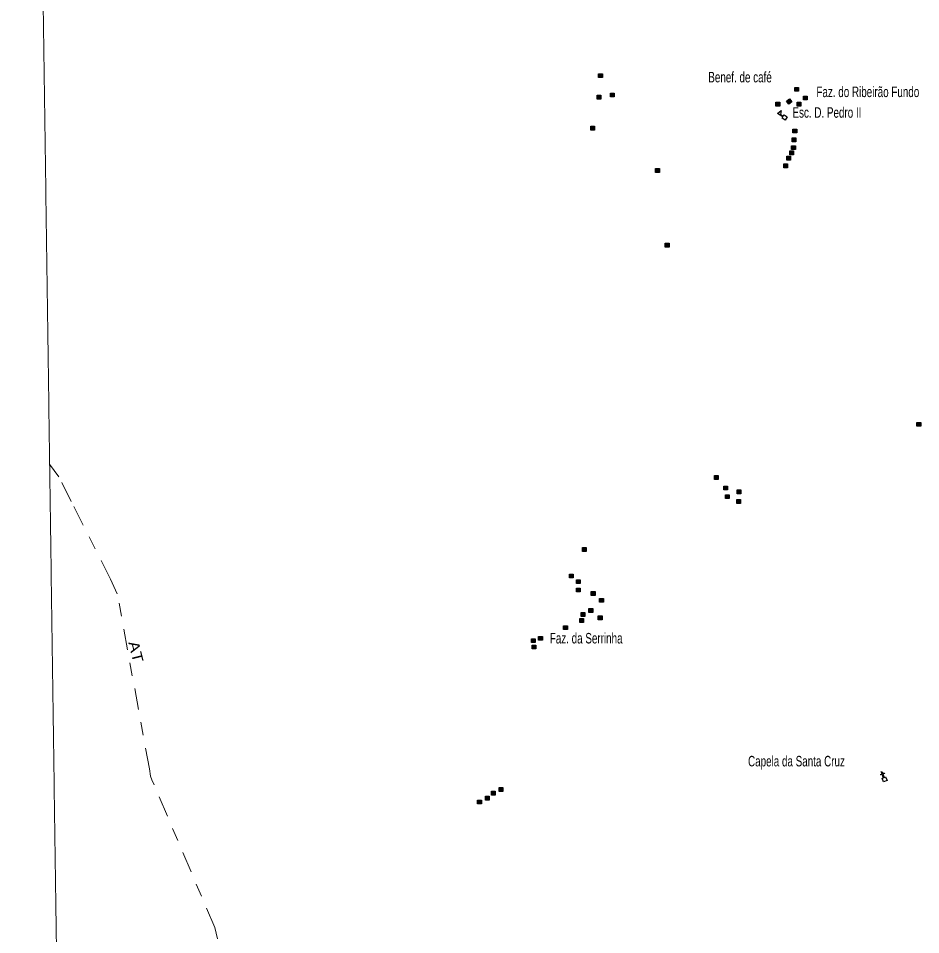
# Model space of a CAD drawing. Extents: x 265.7 to 292.1, y 7676.2 to 7704.2.
# Drawn here: x 265.72 to 272.58, y 7683.22 to 7690.19 of the extents above; entities that cross this region are included whole.
import ezdxf
from ezdxf.enums import TextEntityAlignment as Align

# ---------------------------------------------------------------- set-up
doc = ezdxf.new("R2010")
doc.units = 0
doc.header["$LTSCALE"] = 0.032
doc.linetypes.add('DOT_DASHED', pattern=[7.7, 5, -1.2, 0.3, -1.2])
for name, color, linetype, lineweight in [('2', 7, 'Continuous', 25), ('4', 7, 'Continuous', 25), ('56', 7, 'DOT_DASHED', 13), ('6', 7, 'Continuous', 25), ('63', 7, 'Continuous', 13)]:
    doc.layers.add(name, color=color, linetype=linetype, lineweight=lineweight)
doc.layers.add('61', color=7, linetype='Continuous')

msp = doc.modelspace()

# ---------------------------------------------------------------- hatches: boundary and pattern name
at = {"layer": '2'}
for points in [[(270.1334, 7689.7687), (270.1624, 7689.7687), (270.1624, 7689.7397), (270.1334, 7689.7397)], [(271.6248, 7689.6646), (271.6538, 7689.6646), (271.6538, 7689.6356), (271.6248, 7689.6356)], [(270.1213, 7689.6056), (270.1503, 7689.6056), (270.1503, 7689.5766), (270.1213, 7689.5766)], [(270.2228, 7689.6219), (270.2518, 7689.6219), (270.2518, 7689.5929), (270.2228, 7689.5929)], [(271.5633, 7689.5606), (271.5863, 7689.5783), (271.6039, 7689.5552), (271.5809, 7689.5376)], [(271.6917, 7689.5993), (271.7207, 7689.5993), (271.7207, 7689.5703), (271.6917, 7689.5703)], [(271.4819, 7689.5525), (271.5109, 7689.5525), (271.5109, 7689.5235), (271.4819, 7689.5235)], [(271.6425, 7689.5523), (271.6715, 7689.5523), (271.6715, 7689.5233), (271.6425, 7689.5233)], [(270.0728, 7689.37), (270.1018, 7689.37), (270.1018, 7689.341), (270.0728, 7689.341)], [(271.6118, 7689.3482), (271.6408, 7689.3482), (271.6408, 7689.3192), (271.6118, 7689.3192)], [(271.6013, 7689.2216), (271.6303, 7689.2216), (271.6303, 7689.1926), (271.6013, 7689.1926)], [(271.6046, 7689.2804), (271.6336, 7689.2804), (271.6336, 7689.2514), (271.6046, 7689.2514)], [(271.5876, 7689.1819), (271.6166, 7689.1819), (271.6166, 7689.1529), (271.5876, 7689.1529)], [(271.5416, 7689.0828), (271.5706, 7689.0828), (271.5706, 7689.0538), (271.5416, 7689.0538)], [(271.565, 7689.1409), (271.594, 7689.1409), (271.594, 7689.1119), (271.565, 7689.1119)], [(270.5666, 7689.0472), (270.5956, 7689.0472), (270.5956, 7689.0182), (270.5666, 7689.0182)], [(270.6402, 7688.4798), (270.6692, 7688.4798), (270.6692, 7688.4508), (270.6402, 7688.4508)], [(272.5544, 7687.1167), (272.5834, 7687.1167), (272.5834, 7687.0877), (272.5544, 7687.0877)], [(271.0146, 7686.7124), (271.0436, 7686.7124), (271.0436, 7686.6834), (271.0146, 7686.6834)], [(271.0856, 7686.6326), (271.1146, 7686.6326), (271.1146, 7686.6036), (271.0856, 7686.6036)], [(271.1868, 7686.6028), (271.2158, 7686.6028), (271.2158, 7686.5738), (271.1868, 7686.5738)], [(271.0984, 7686.567), (271.1274, 7686.567), (271.1274, 7686.538), (271.0984, 7686.538)], [(271.1842, 7686.5301), (271.2132, 7686.5301), (271.2132, 7686.5011), (271.1842, 7686.5011)], [(270.0099, 7686.1652), (270.0389, 7686.1652), (270.0389, 7686.1362), (270.0099, 7686.1362)], [(269.9106, 7685.9628), (269.9396, 7685.9628), (269.9396, 7685.9338), (269.9106, 7685.9338)], [(269.9638, 7685.9199), (269.9928, 7685.9199), (269.9928, 7685.8909), (269.9638, 7685.8909)], [(269.9638, 7685.857), (269.9928, 7685.857), (269.9928, 7685.828), (269.9638, 7685.828)], [(270.0776, 7685.8296), (270.1066, 7685.8296), (270.1066, 7685.8006), (270.0776, 7685.8006)], [(270.1406, 7685.7778), (270.1696, 7685.7778), (270.1696, 7685.7488), (270.1406, 7685.7488)], [(269.9994, 7685.6705), (270.0284, 7685.6705), (270.0284, 7685.6415), (269.9994, 7685.6415)], [(270.0592, 7685.7004), (270.0882, 7685.7004), (270.0882, 7685.6714), (270.0592, 7685.6714)], [(269.9896, 7685.6251), (270.0186, 7685.6251), (270.0186, 7685.5961), (269.9896, 7685.5961)], [(270.1308, 7685.645), (270.1598, 7685.645), (270.1598, 7685.616), (270.1308, 7685.616)], [(269.8662, 7685.5697), (269.8952, 7685.5697), (269.8952, 7685.5407), (269.8662, 7685.5407)], [(269.6217, 7685.4712), (269.6507, 7685.4712), (269.6507, 7685.4422), (269.6217, 7685.4422)], [(269.6762, 7685.4885), (269.7052, 7685.4885), (269.7052, 7685.4595), (269.6762, 7685.4595)], [(269.6266, 7685.4235), (269.6556, 7685.4235), (269.6556, 7685.3945), (269.6266, 7685.3945)], [(269.2722, 7684.2735), (269.3012, 7684.2735), (269.3012, 7684.2445), (269.2722, 7684.2445)], [(269.3174, 7684.3107), (269.3464, 7684.3107), (269.3464, 7684.2817), (269.3174, 7684.2817)], [(269.3754, 7684.3396), (269.4044, 7684.3396), (269.4044, 7684.3106), (269.3754, 7684.3106)], [(269.2125, 7684.2445), (269.2415, 7684.2445), (269.2415, 7684.2155), (269.2125, 7684.2155)]]:
    msp.add_hatch(color=256, dxfattribs=at).paths.add_polyline_path(points)

# ---------------------------------------------------------------- linework, layer by layer
for points in [[(270.1334, 7689.7687), (270.1624, 7689.7687), (270.1624, 7689.7397), (270.1334, 7689.7397)], [(271.6248, 7689.6646), (271.6538, 7689.6646), (271.6538, 7689.6356), (271.6248, 7689.6356)], [(270.1213, 7689.6056), (270.1503, 7689.6056), (270.1503, 7689.5766), (270.1213, 7689.5766)], [(270.2228, 7689.6219), (270.2518, 7689.6219), (270.2518, 7689.5929), (270.2228, 7689.5929)], [(271.5633, 7689.5606), (271.5863, 7689.5783), (271.6039, 7689.5552), (271.5809, 7689.5376)], [(271.6917, 7689.5993), (271.7207, 7689.5993), (271.7207, 7689.5703), (271.6917, 7689.5703)], [(271.4819, 7689.5525), (271.5109, 7689.5525), (271.5109, 7689.5235), (271.4819, 7689.5235)], [(271.6425, 7689.5523), (271.6715, 7689.5523), (271.6715, 7689.5233), (271.6425, 7689.5233)], [(270.0728, 7689.37), (270.1018, 7689.37), (270.1018, 7689.341), (270.0728, 7689.341)], [(271.6118, 7689.3482), (271.6408, 7689.3482), (271.6408, 7689.3192), (271.6118, 7689.3192)], [(271.6013, 7689.2216), (271.6303, 7689.2216), (271.6303, 7689.1926), (271.6013, 7689.1926)], [(271.6046, 7689.2804), (271.6336, 7689.2804), (271.6336, 7689.2514), (271.6046, 7689.2514)], [(271.5876, 7689.1819), (271.6166, 7689.1819), (271.6166, 7689.1529), (271.5876, 7689.1529)], [(271.5416, 7689.0828), (271.5706, 7689.0828), (271.5706, 7689.0538), (271.5416, 7689.0538)], [(271.565, 7689.1409), (271.594, 7689.1409), (271.594, 7689.1119), (271.565, 7689.1119)], [(270.5666, 7689.0472), (270.5956, 7689.0472), (270.5956, 7689.0182), (270.5666, 7689.0182)], [(270.6402, 7688.4798), (270.6692, 7688.4798), (270.6692, 7688.4508), (270.6402, 7688.4508)], [(272.5544, 7687.1167), (272.5834, 7687.1167), (272.5834, 7687.0877), (272.5544, 7687.0877)], [(271.0146, 7686.7124), (271.0436, 7686.7124), (271.0436, 7686.6834), (271.0146, 7686.6834)], [(271.0856, 7686.6326), (271.1146, 7686.6326), (271.1146, 7686.6036), (271.0856, 7686.6036)], [(271.1868, 7686.6028), (271.2158, 7686.6028), (271.2158, 7686.5738), (271.1868, 7686.5738)], [(271.0984, 7686.567), (271.1274, 7686.567), (271.1274, 7686.538), (271.0984, 7686.538)], [(271.1842, 7686.5301), (271.2132, 7686.5301), (271.2132, 7686.5011), (271.1842, 7686.5011)], [(270.0099, 7686.1652), (270.0389, 7686.1652), (270.0389, 7686.1362), (270.0099, 7686.1362)], [(269.9106, 7685.9628), (269.9396, 7685.9628), (269.9396, 7685.9338), (269.9106, 7685.9338)], [(269.9638, 7685.9199), (269.9928, 7685.9199), (269.9928, 7685.8909), (269.9638, 7685.8909)], [(269.9638, 7685.857), (269.9928, 7685.857), (269.9928, 7685.828), (269.9638, 7685.828)], [(270.0776, 7685.8296), (270.1066, 7685.8296), (270.1066, 7685.8006), (270.0776, 7685.8006)], [(270.1406, 7685.7778), (270.1696, 7685.7778), (270.1696, 7685.7488), (270.1406, 7685.7488)], [(269.9994, 7685.6705), (270.0284, 7685.6705), (270.0284, 7685.6415), (269.9994, 7685.6415)], [(270.0592, 7685.7004), (270.0882, 7685.7004), (270.0882, 7685.6714), (270.0592, 7685.6714)], [(269.9896, 7685.6251), (270.0186, 7685.6251), (270.0186, 7685.5961), (269.9896, 7685.5961)], [(270.1308, 7685.645), (270.1598, 7685.645), (270.1598, 7685.616), (270.1308, 7685.616)], [(269.8662, 7685.5697), (269.8952, 7685.5697), (269.8952, 7685.5407), (269.8662, 7685.5407)], [(269.6217, 7685.4712), (269.6507, 7685.4712), (269.6507, 7685.4422), (269.6217, 7685.4422)], [(269.6762, 7685.4885), (269.7052, 7685.4885), (269.7052, 7685.4595), (269.6762, 7685.4595)], [(269.6266, 7685.4235), (269.6556, 7685.4235), (269.6556, 7685.3945), (269.6266, 7685.3945)], [(269.2722, 7684.2735), (269.3012, 7684.2735), (269.3012, 7684.2445), (269.2722, 7684.2445)], [(269.3174, 7684.3107), (269.3464, 7684.3107), (269.3464, 7684.2817), (269.3174, 7684.2817)], [(269.3754, 7684.3396), (269.4044, 7684.3396), (269.4044, 7684.3106), (269.3754, 7684.3106)], [(269.2125, 7684.2445), (269.2415, 7684.2445), (269.2415, 7684.2155), (269.2125, 7684.2155)]]:
    msp.add_lwpolyline(points, close=True, dxfattribs=at)
at = {"layer": '4'}
for points in [[(271.5352, 7689.4415), (271.4943, 7689.4674), (271.5223, 7689.4899), (271.5158, 7689.4596), (271.5379, 7689.4457)], [(271.5379, 7689.4457), (271.5443, 7689.4559), (271.5688, 7689.4404), (271.5533, 7689.4159), (271.5288, 7689.4314), (271.5352, 7689.4415)]]:
    msp.add_lwpolyline(points, dxfattribs=at)
at = {"layer": '56'}
msp.add_lwpolyline([(267.3403, 7682.7419), (267.2124, 7683.2739), (266.7346, 7684.3993), (266.7236, 7684.425), (266.7154, 7684.4819), (266.4706, 7685.8138), (266.4194, 7685.9244), (266.121, 7686.5156), (266.0273, 7686.7034), (265.9563, 7686.7985)], dxfattribs=at)
at = {"layer": '6'}
for points in [[(272.3009, 7684.4143), (272.2911, 7684.4396), (272.2799, 7684.4352), (272.2781, 7684.4397), (272.2894, 7684.4441), (272.2834, 7684.4594), (272.288, 7684.4611), (272.2939, 7684.4458), (272.3051, 7684.4502), (272.3069, 7684.4456), (272.2957, 7684.4412), (272.3054, 7684.416)], [(272.3054, 7684.416), (272.3167, 7684.4203), (272.3272, 7684.3933), (272.3002, 7684.3828), (272.2897, 7684.4099), (272.3009, 7684.4143)]]:
    msp.add_lwpolyline(points, dxfattribs=at)
at = {"layer": '63'}
msp.add_spline([(266.1055, 7676.1764), (266.0976, 7676.7414), (266.0896, 7677.3064), (266.0817, 7677.8713), (266.0737, 7678.4363), (266.0658, 7679.0013), (266.0578, 7679.5663), (266.0499, 7680.1313), (266.0419, 7680.6963), (266.034, 7681.2613), (266.026, 7681.8263), (266.0181, 7682.3913), (266.0102, 7682.9563), (266.0022, 7683.5212), (265.9943, 7684.0862), (265.9864, 7684.6512), (265.9785, 7685.2162), (265.9705, 7685.7812), (265.9626, 7686.3462), (265.9547, 7686.9112), (265.9468, 7687.4762), (265.9389, 7688.0411), (265.9309, 7688.6061), (265.923, 7689.1711), (265.9151, 7689.7361), (265.9072, 7690.3011), (265.8993, 7690.8661), (265.8914, 7691.4311), (265.8835, 7691.996), (265.8756, 7692.561), (265.8677, 7693.126), (265.8598, 7693.691), (265.8519, 7694.256), (265.844, 7694.821), (265.8361, 7695.3859), (265.8282, 7695.9509), (265.8203, 7696.5159), (265.8124, 7697.0809), (265.8045, 7697.6459), (265.7967, 7698.2108), (265.7888, 7698.7758), (265.7809, 7699.3408), (265.773, 7699.9058), (265.7651, 7700.4708), (265.7573, 7701.0357), (265.7494, 7701.6007), (265.7415, 7702.1657), (265.7337, 7702.7307), (265.7258, 7703.2957), (265.7179, 7703.8606)], degree=3, dxfattribs=at)

# ---------------------------------------------------------------- texts
at = {"layer": '61', "width": 0.7}
for s, p in [('Benef. de café', (270.9676, 7689.7034)), ('Faz. do Ribeirão Fundo', (271.7901, 7689.5915)), ('Esc. D. Pedro II', (271.608, 7689.4346)), ('Faz. da Serrinha', (269.7615, 7685.4355)), ('Capela da Santa Cruz', (271.27, 7684.5002))]:
    msp.add_text(s, height=0.08, dxfattribs=at).set_placement(p)
at = {"layer": '61', "width": 1.2}
msp.add_text('AT', height=0.08, rotation=283.988, dxfattribs=at).set_placement((266.5736, 7685.3632), align=Align.CENTER)

doc.saveas('drawing.dxf')
